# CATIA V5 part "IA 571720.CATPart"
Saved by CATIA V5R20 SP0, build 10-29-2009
Part number: IA 571720
Revision: ANY
Definition: UNKNOWN
Nomenclature: IA 571720
Source: Unknown
Bounding box of the stored display mesh (mm): x -2.85 to 2.85, y -7.925 to 9.045, z -2.711 to 2.711
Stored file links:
  C:\Users\Utente\Desktop\IO LAVORO\3D X SITO CF\CUMSA\3D files FA\FA 105712-20\IA 571720.CATPart
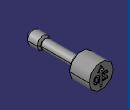
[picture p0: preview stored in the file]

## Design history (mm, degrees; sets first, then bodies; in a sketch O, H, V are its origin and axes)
Body1 "Cortar-Extruir4" (main body)
  Solid1: solid without history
